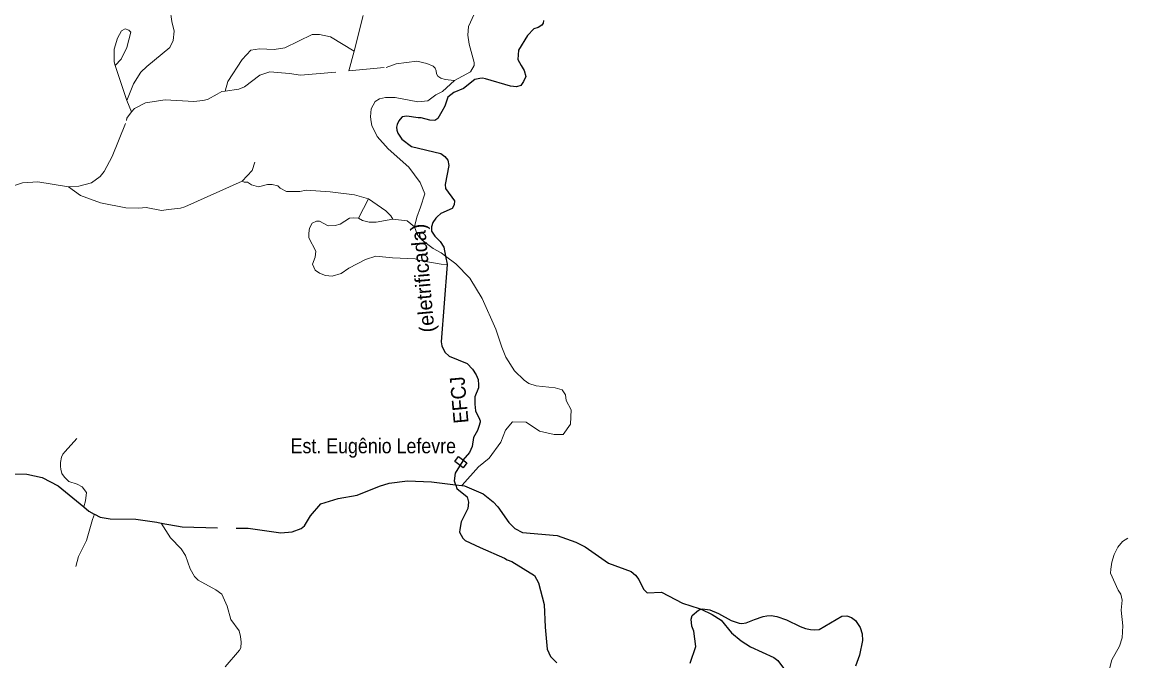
# Model space of a CAD drawing. Extents: x 423 to 448.8, y 7456.3 to 7484.
# Drawn here: x 433.23 to 439.2, y 7474.65 to 7478.1 of the extents above; entities that cross this region are included whole.
import ezdxf
from ezdxf.enums import TextEntityAlignment as Align

# ---------------------------------------------------------------- set-up
doc = ezdxf.new("R2010")
doc.units = 0
doc.header["$LTSCALE"] = 0.032
doc.linetypes.add('LONG_DASHED', pattern=[7.5, 6, -1.5])
for name, color, linetype, lineweight in [('15', 7, 'Continuous', 25), ('28', 7, 'Continuous', 25), ('4', 7, 'LONG_DASHED', 25), ('5', 7, 'LONG_DASHED', 13), ('7', 7, 'Continuous', 13)]:
    doc.layers.add(name, color=color, linetype=linetype, lineweight=lineweight)
doc.layers.add('61', color=7, linetype='Continuous')

msp = doc.modelspace()

# ---------------------------------------------------------------- linework, layer by layer
at = {"layer": '15'}
for points in [[(436.0448, 7478.1089), (436.0431, 7478.0943), (436.0368, 7478.0839), (436.0166, 7478.0706), (435.993, 7478.064), (435.9587, 7478.0276), (435.9094, 7477.9484), (435.9064, 7477.8985), (435.9248, 7477.8655), (435.9413, 7477.8386), (435.9499, 7477.806), (435.9365, 7477.7788), (435.922, 7477.7568), (435.9002, 7477.7504), (435.8675, 7477.7536), (435.7318, 7477.7936), (435.7156, 7477.7964), (435.7007, 7477.796), (435.6736, 7477.79), (435.6125, 7477.7405), (435.5602, 7477.7193), (435.5274, 7477.6954), (435.5115, 7477.6465), (435.4961, 7477.6171), (435.4734, 7477.5785), (435.4588, 7477.5692), (435.4317, 7477.5697), (435.3836, 7477.5822), (435.3679, 7477.583), (435.3066, 7477.5914), (435.2809, 7477.5879), (435.2706, 7477.5758), (435.2632, 7477.567), (435.2548, 7477.547), (435.2512, 7477.5327), (435.2525, 7477.5169), (435.2587, 7477.5005), (435.2796, 7477.4672), (435.3323, 7477.4286), (435.4905, 7477.3894), (435.5128, 7477.3748), (435.5274, 7477.3542), (435.5334, 7477.3251), (435.5145, 7477.2237), (435.5162, 7477.2014), (435.5639, 7477.1338), (435.562, 7477.113), (435.5519, 7477.0936), (435.4905, 7477.0657), (435.4698, 7477.0476), (435.4626, 7477.0415), (435.4466, 7477.0176), (435.4398, 7476.9947), (435.4391, 7476.9705), (435.4572, 7476.9444), (435.487, 7476.9145), (435.5059, 7476.8836), (435.5163, 7476.8349), (435.5253, 7476.7926), (435.5252, 7476.7911), (435.493, 7476.3735), (435.4964, 7476.3511), (435.5119, 7476.3176), (435.5351, 7476.2962), (435.6324, 7476.2557), (435.6612, 7476.2261), (435.681, 7476.1952), (435.692, 7476.1691), (435.694, 7476.1416), (435.694, 7476.1252)], [(435.694, 7476.1252), (435.6746, 7476.0761), (435.6741, 7476.037), (435.6786, 7476.0005), (435.6992, 7475.9561), (435.7031, 7475.9458), (435.7023, 7475.9387), (435.695, 7475.9149), (435.689, 7475.8939), (435.6676, 7475.8556), (435.6605, 7475.8083), (435.6459, 7475.7748), (435.609, 7475.7336), (435.609, 7475.731), (435.5686, 7475.6632), (435.5616, 7475.6222), (435.5703, 7475.6004), (435.5707, 7475.5994), (435.576, 7475.5805), (435.6324, 7475.5364), (435.6404, 7475.5065), (435.6364, 7475.4726), (435.6001, 7475.4003), (435.5926, 7475.3602), (435.5909, 7475.3454), (435.6098, 7475.3128), (435.6218, 7475.3007), (435.7031, 7475.2622), (435.834, 7475.2054), (435.8486, 7475.1951), (435.8744, 7475.1857), (435.9964, 7475.1102), (436.0178, 7475.0721), (436.0495, 7474.9547), (436.054, 7474.8311), (436.0652, 7474.7135), (436.0839, 7474.673), (436.1165, 7474.6386)], [(436.838, 7474.6368), (436.868, 7474.7279), (436.8585, 7474.8095), (436.8465, 7474.8379), (436.8431, 7474.8756), (436.8491, 7474.8945), (436.8824, 7474.9232), (436.8967, 7474.9282), (436.9053, 7474.9312), (436.9442, 7474.9252), (436.9902, 7474.906), (437.0587, 7474.868), (437.1019, 7474.853), (437.1171, 7474.8514), (437.1397, 7474.8559), (437.1861, 7474.8735), (437.233, 7474.8895), (437.2517, 7474.8939), (437.2756, 7474.8944), (437.3053, 7474.8895), (437.3577, 7474.8707), (437.4316, 7474.8349), (437.4608, 7474.8238), (437.4876, 7474.819), (437.5121, 7474.8172), (437.5344, 7474.819), (437.6582, 7474.8914), (437.684, 7474.8932), (437.7099, 7474.8834), (437.732, 7474.867), (437.7569, 7474.8309), (437.7681, 7474.7962), (437.7683, 7474.7599), (437.7535, 7474.6807), (437.7315, 7474.6205)]]:
    msp.add_lwpolyline(points, dxfattribs=at)
at = {"layer": '28'}
msp.add_lwpolyline([(435.5861, 7475.7533), (435.6318, 7475.7192), (435.6116, 7475.692), (435.5658, 7475.7261)], close=True, dxfattribs=at)
at = {"layer": '4'}
for points in [[(433.1166, 7475.6611), (433.254, 7475.6589), (433.3365, 7475.64), (433.4224, 7475.5945), (433.5606, 7475.4811), (433.589, 7475.4579), (433.6176, 7475.4426), (433.619, 7475.4416), (433.6491, 7475.4253), (433.7041, 7475.4167), (433.8415, 7475.415), (433.9553, 7475.3982), (433.9796, 7475.3938)], [(433.9796, 7475.3938), (434.0918, 7475.3733), (434.4491, 7475.3657), (434.6263, 7475.342), (434.6866, 7475.3463), (434.7364, 7475.3643), (434.7544, 7475.3789), (434.787, 7475.4339), (434.8412, 7475.4974), (434.9357, 7475.5266), (435.0387, 7475.5455), (435.159, 7475.5936), (435.2105, 7475.6091), (435.3101, 7475.6219), (435.4406, 7475.6162), (435.5703, 7475.6004), (435.6037, 7475.5963), (435.6187, 7475.5947), (435.7189, 7475.5524), (435.773, 7475.5086), (435.7979, 7475.4811), (435.8571, 7475.3978), (435.8898, 7475.3651), (435.9319, 7475.3437), (436.1191, 7475.3265), (436.2205, 7475.2913), (436.2703, 7475.2655), (436.3957, 7475.177), (436.5194, 7475.1316), (436.5417, 7475.1135), (436.5597, 7475.0886), (436.5854, 7475.0371), (436.6061, 7475.0173), (436.6834, 7475.0216), (436.7959, 7474.9606), (436.886, 7474.9331), (436.8967, 7474.9282), (436.9562, 7474.9009), (437.0046, 7474.8701), (437.0604, 7474.8017), (437.1137, 7474.7571), (437.1643, 7474.7262), (437.2906, 7474.6686), (437.312, 7474.6514), (437.3773, 7474.5613)]]:
    msp.add_lwpolyline(points, dxfattribs=at)
at = {"layer": '5'}
for points in [[(435.6699, 7478.1428), (435.6394, 7478.077), (435.6357, 7478.0293), (435.644, 7477.9801), (435.6699, 7477.8816), (435.6699, 7477.8661), (435.6502, 7477.8318), (435.5638, 7477.7849)], [(433.1338, 7477.1996), (433.23, 7477.2314), (433.3124, 7477.2374), (433.4791, 7477.2108), (433.534, 7477.2142), (433.6027, 7477.2323), (433.6491, 7477.2666), (433.6705, 7477.2924), (433.7144, 7477.3749), (433.7925, 7477.5681), (433.7942, 7477.581), (433.8183, 7477.6153), (433.8355, 7477.6334), (433.8939, 7477.6637), (434.0003, 7477.6806), (434.1558, 7477.672), (434.2039, 7477.6763), (434.2297, 7477.6823), (434.2812, 7477.7115), (434.307, 7477.7244), (434.3254, 7477.727), (434.398, 7477.7373), (434.4289, 7477.751), (434.5131, 7477.8129), (434.5655, 7477.8322), (434.6728, 7477.8232), (434.7314, 7477.8129), (434.9936, 7477.8366), (435.1946, 7477.8548), (435.2482, 7477.8743), (435.3611, 7477.8896), (435.4148, 7477.8757), (435.4481, 7477.8618), (435.4596, 7477.8508), (435.4656, 7477.8368), (435.4672, 7477.8202), (435.4749, 7477.8076), (435.4905, 7477.7977), (435.5139, 7477.7901), (435.5618, 7477.7854), (435.5638, 7477.7849)], [(435.5638, 7477.7849), (435.4999, 7477.7256), (435.4629, 7477.7066), (435.4203, 7477.6751), (435.3668, 7477.6694), (435.2431, 7477.6935), (435.1916, 7477.6935), (435.1581, 7477.6858), (435.1357, 7477.6711), (435.1143, 7477.6308), (435.1099, 7477.5879), (435.1134, 7477.5621), (435.1177, 7477.5423), (435.1461, 7477.4814), (435.2062, 7477.4161), (435.317, 7477.3164), (435.3788, 7477.234), (435.4037, 7477.173), (435.3813, 7477.1), (435.3607, 7477.0468), (435.3487, 7476.9946), (435.3631, 7476.9537), (435.3749, 7476.9363), (435.3892, 7476.9222), (435.4487, 7476.8777), (435.4922, 7476.853), (435.5163, 7476.8349), (435.5714, 7476.7935), (435.6476, 7476.7176), (435.7146, 7476.6071), (435.7876, 7476.4422), (435.8194, 7476.3434), (435.8417, 7476.291), (435.8889, 7476.2171), (435.9405, 7476.1664), (435.9666, 7476.1482), (436.0049, 7476.1355), (436.1088, 7476.1244), (436.1458, 7476.1141), (436.1638, 7476.0866), (436.1686, 7476.0568), (436.1943, 7476.0053), (436.1919, 7475.9281), (436.1522, 7475.872), (436.1032, 7475.872), (436.0239, 7475.8907), (435.9515, 7475.9398), (435.878, 7475.9404), (435.8407, 7475.896), (435.815, 7475.8307), (435.752, 7475.7443), (435.6936, 7475.6976), (435.6054, 7475.5982), (435.6037, 7475.5963)]]:
    msp.add_lwpolyline(points, dxfattribs=at)
at = {"layer": '7'}
msp.add_line((435.0456, 7477.0403), (435.1003, 7477.1448), dxfattribs=at)
for points in [[(433.7943, 7477.6764), (433.8295, 7477.7667), (433.8699, 7477.8288), (433.9018, 7477.8608), (434.0261, 7477.9633), (434.0446, 7478.0002), (434.0497, 7478.0506), (434.0364, 7478.1032), (434.0194, 7478.2355), (434.0312, 7478.2691), (434.1438, 7478.3649), (434.2244, 7478.4724), (434.2916, 7478.5716), (434.3538, 7478.6169), (434.4126, 7478.6354), (434.4748, 7478.6354), (434.5571, 7478.5968), (434.6412, 7478.5396), (434.7819, 7478.4688)], [(434.9936, 7477.8366), (435.0212, 7477.9439), (435.0702, 7478.1365)], [(434.3254, 7477.727), (434.3387, 7477.7784), (434.4177, 7477.8977), (434.463, 7477.9481), (434.5101, 7477.9565), (434.5891, 7477.9515), (434.6479, 7477.9616), (434.7957, 7478.0322), (434.8344, 7478.0322), (434.8949, 7478.0204), (435.0212, 7477.9439)], [(433.8183, 7477.6153), (433.7943, 7477.6764), (433.7312, 7477.8661)], [(434.4169, 7477.2409), (434.4701, 7477.2993), (434.4856, 7477.3431)], [(434.4169, 7477.2409), (434.1077, 7477.1026), (434.0845, 7477.0957), (434.0192, 7477.088), (433.9807, 7477.083), (433.8982, 7477.0992), (433.8587, 7477.0949), (433.7882, 7477.0974), (433.6508, 7477.1241), (433.5434, 7477.1627), (433.4791, 7477.2108)], [(435.1003, 7477.1448), (435.0234, 7477.1666), (434.8918, 7477.1836), (434.7619, 7477.1927), (434.7286, 7477.1859), (434.6565, 7477.1859), (434.6222, 7477.2031), (434.6093, 7477.2159), (434.5784, 7477.2237), (434.5543, 7477.2228), (434.5045, 7477.21), (434.4675, 7477.2203), (434.4461, 7477.2349), (434.4272, 7477.2357), (434.4169, 7477.2409)], [(435.2316, 7477.0351), (435.2207, 7477.053), (435.1938, 7477.0799), (435.1003, 7477.1448)], [(435.0456, 7477.0403), (435.0192, 7477.0429), (434.9975, 7477.0407), (434.9468, 7477.009), (434.9193, 7477.0021), (434.8815, 7476.9995), (434.8343, 7477.0244), (434.819, 7477.0245), (434.7956, 7477.0133), (434.781, 7476.9867), (434.7768, 7476.9601), (434.7776, 7476.9351), (434.8145, 7476.863), (434.812, 7476.8295), (434.7974, 7476.7926), (434.8111, 7476.7608), (434.8343, 7476.7436), (434.8678, 7476.7316), (434.903, 7476.7281), (434.9519, 7476.7427), (434.9932, 7476.7711), (435.0827, 7476.8185), (435.14, 7476.835), (435.2298, 7476.826), (435.3522, 7476.8213), (435.3769, 7476.813), (435.4915, 7476.7918), (435.5252, 7476.7911)], [(435.2316, 7477.0351), (435.1409, 7477.0193), (435.104, 7477.0193), (435.0679, 7477.0279), (435.0456, 7477.0403)], [(435.3487, 7476.9946), (435.3093, 7477.0261), (435.2316, 7477.0351)], [(433.5606, 7475.4811), (433.5702, 7475.5139), (433.5754, 7475.5588), (433.552, 7475.5895), (433.5251, 7475.6045), (433.4803, 7475.6184), (433.4567, 7475.6417), (433.4421, 7475.6614), (433.4369, 7475.6847), (433.4349, 7475.6997), (433.4351, 7475.7218), (433.4411, 7475.7497), (433.4475, 7475.767), (433.4605, 7475.7803), (433.5227, 7475.8507)], [(433.619, 7475.4416), (433.6083, 7475.4133), (433.5753, 7475.3005), (433.532, 7475.214), (433.5172, 7475.1604)], [(433.9796, 7475.3938), (434.03, 7475.3141), (434.0865, 7475.2543), (434.1103, 7475.2183), (434.136, 7475.1461), (434.1593, 7475.1058), (434.179, 7475.086), (434.2743, 7475.0336), (434.3061, 7475.0104), (434.3361, 7474.9461), (434.3551, 7474.873), (434.4006, 7474.8121), (434.4083, 7474.7812), (434.4118, 7474.7511), (434.4092, 7474.721), (434.4031, 7474.7073), (434.325, 7474.6171)], [(439.0856, 7474.5364), (439.1173, 7474.6558), (439.1577, 7474.7296), (439.1715, 7474.7734), (439.1766, 7474.8396), (439.1671, 7474.9237), (439.1731, 7474.977), (439.1645, 7475.0096), (439.1499, 7475.031), (439.1091, 7475.1233), (439.1105, 7475.1453), (439.1156, 7475.1831), (439.1285, 7475.2243), (439.1482, 7475.2647), (439.174, 7475.2947), (439.2032, 7475.3127)]]:
    msp.add_lwpolyline(points, dxfattribs=at)
msp.add_lwpolyline([(433.7312, 7477.8661), (433.7255, 7477.8863), (433.7255, 7477.9537), (433.7434, 7478.0138), (433.7655, 7478.0528), (433.7845, 7478.0633), (433.8045, 7478.057), (433.815, 7478.0465), (433.794, 7477.9632), (433.7634, 7477.9)], close=True, dxfattribs=at)

# ---------------------------------------------------------------- texts
at = {"layer": '61'}
msp.add_text('(eletrificada)', height=0.08, rotation=95.106, dxfattribs=at).set_placement((435.4306, 7476.7203), align=Align.CENTER)
at = {"layer": '61', "width": 0.95}
msp.add_text('EFCJ', height=0.08, rotation=95.106, dxfattribs=at).set_placement((435.629, 7476.0624), align=Align.CENTER)
at = {"layer": '61', "width": 0.9}
msp.add_text('Est. Eugênio Lefevre', height=0.08, dxfattribs=at).set_placement((435.5724, 7475.771), align=Align.RIGHT)

doc.saveas('drawing.dxf')
